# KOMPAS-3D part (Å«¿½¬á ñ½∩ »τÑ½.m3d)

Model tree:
1. Эскиз:1
2. Операция вращения:2
     Угол 1 = 360
3. Скругление:3
     Радиус = 1
4. Скругление:4
     Радиус = 5
5. Скругление:5
     Радиус = 0.4
6. Скругление:6
     Радиус = 0.4
7. Скругление:7
     Радиус = 2
8. Эскиз:3
9. Спираль цилиндрическая:2
     Число витков = 2.4; Шаг = 2.7; Высота = 6.48; Диаметр 1 = 28.5; Диаметр 2 = 10
10. Эскиз:4
11. Кинематическая операция:2
12. Эскиз:5
13. Операция выдавливания:3
     Расстояние 1 = 10; Расстояние 2 = 8
14. Эскиз:7
15. Операция выдавливания:4
     Расстояние 1 = 3; Расстояние 2 = 3
16. Эскиз:8
17. Вырезать элемент выдавливания:2
     Расстояние 2 = 25; Расстояние 1 = 25
18. Эскиз:9
19. Вырезать элемент выдавливания:3
     Расстояние 2 = 25; Расстояние 1 = 25
20. Скругление:15
     Радиус = 1
21. Скругление:16
     Радиус = 1
22. Скругление:18
     Радиус = 1
23. Скругление:19
     Радиус = 1
24. Скругление:20
     Радиус = 1
25. Скругление:23
     Радиус = 0.3
26. Скругление:25
     Радиус = 3
27. Скругление:26
     Радиус = 3
28. Скругление:28
     Радиус = 0.45
29. Эскиз:10
30. Операция выдавливания:5
     Расстояние 1 = 7
31. Скругление:29
     Радиус = 1
32. Скругление:30
     Радиус = 1
33. Скругление:31
     Радиус = 1
34. Скругление:32
     Радиус = 1

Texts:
  Поилка для пчел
